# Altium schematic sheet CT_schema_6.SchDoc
size 372 x 336 mm
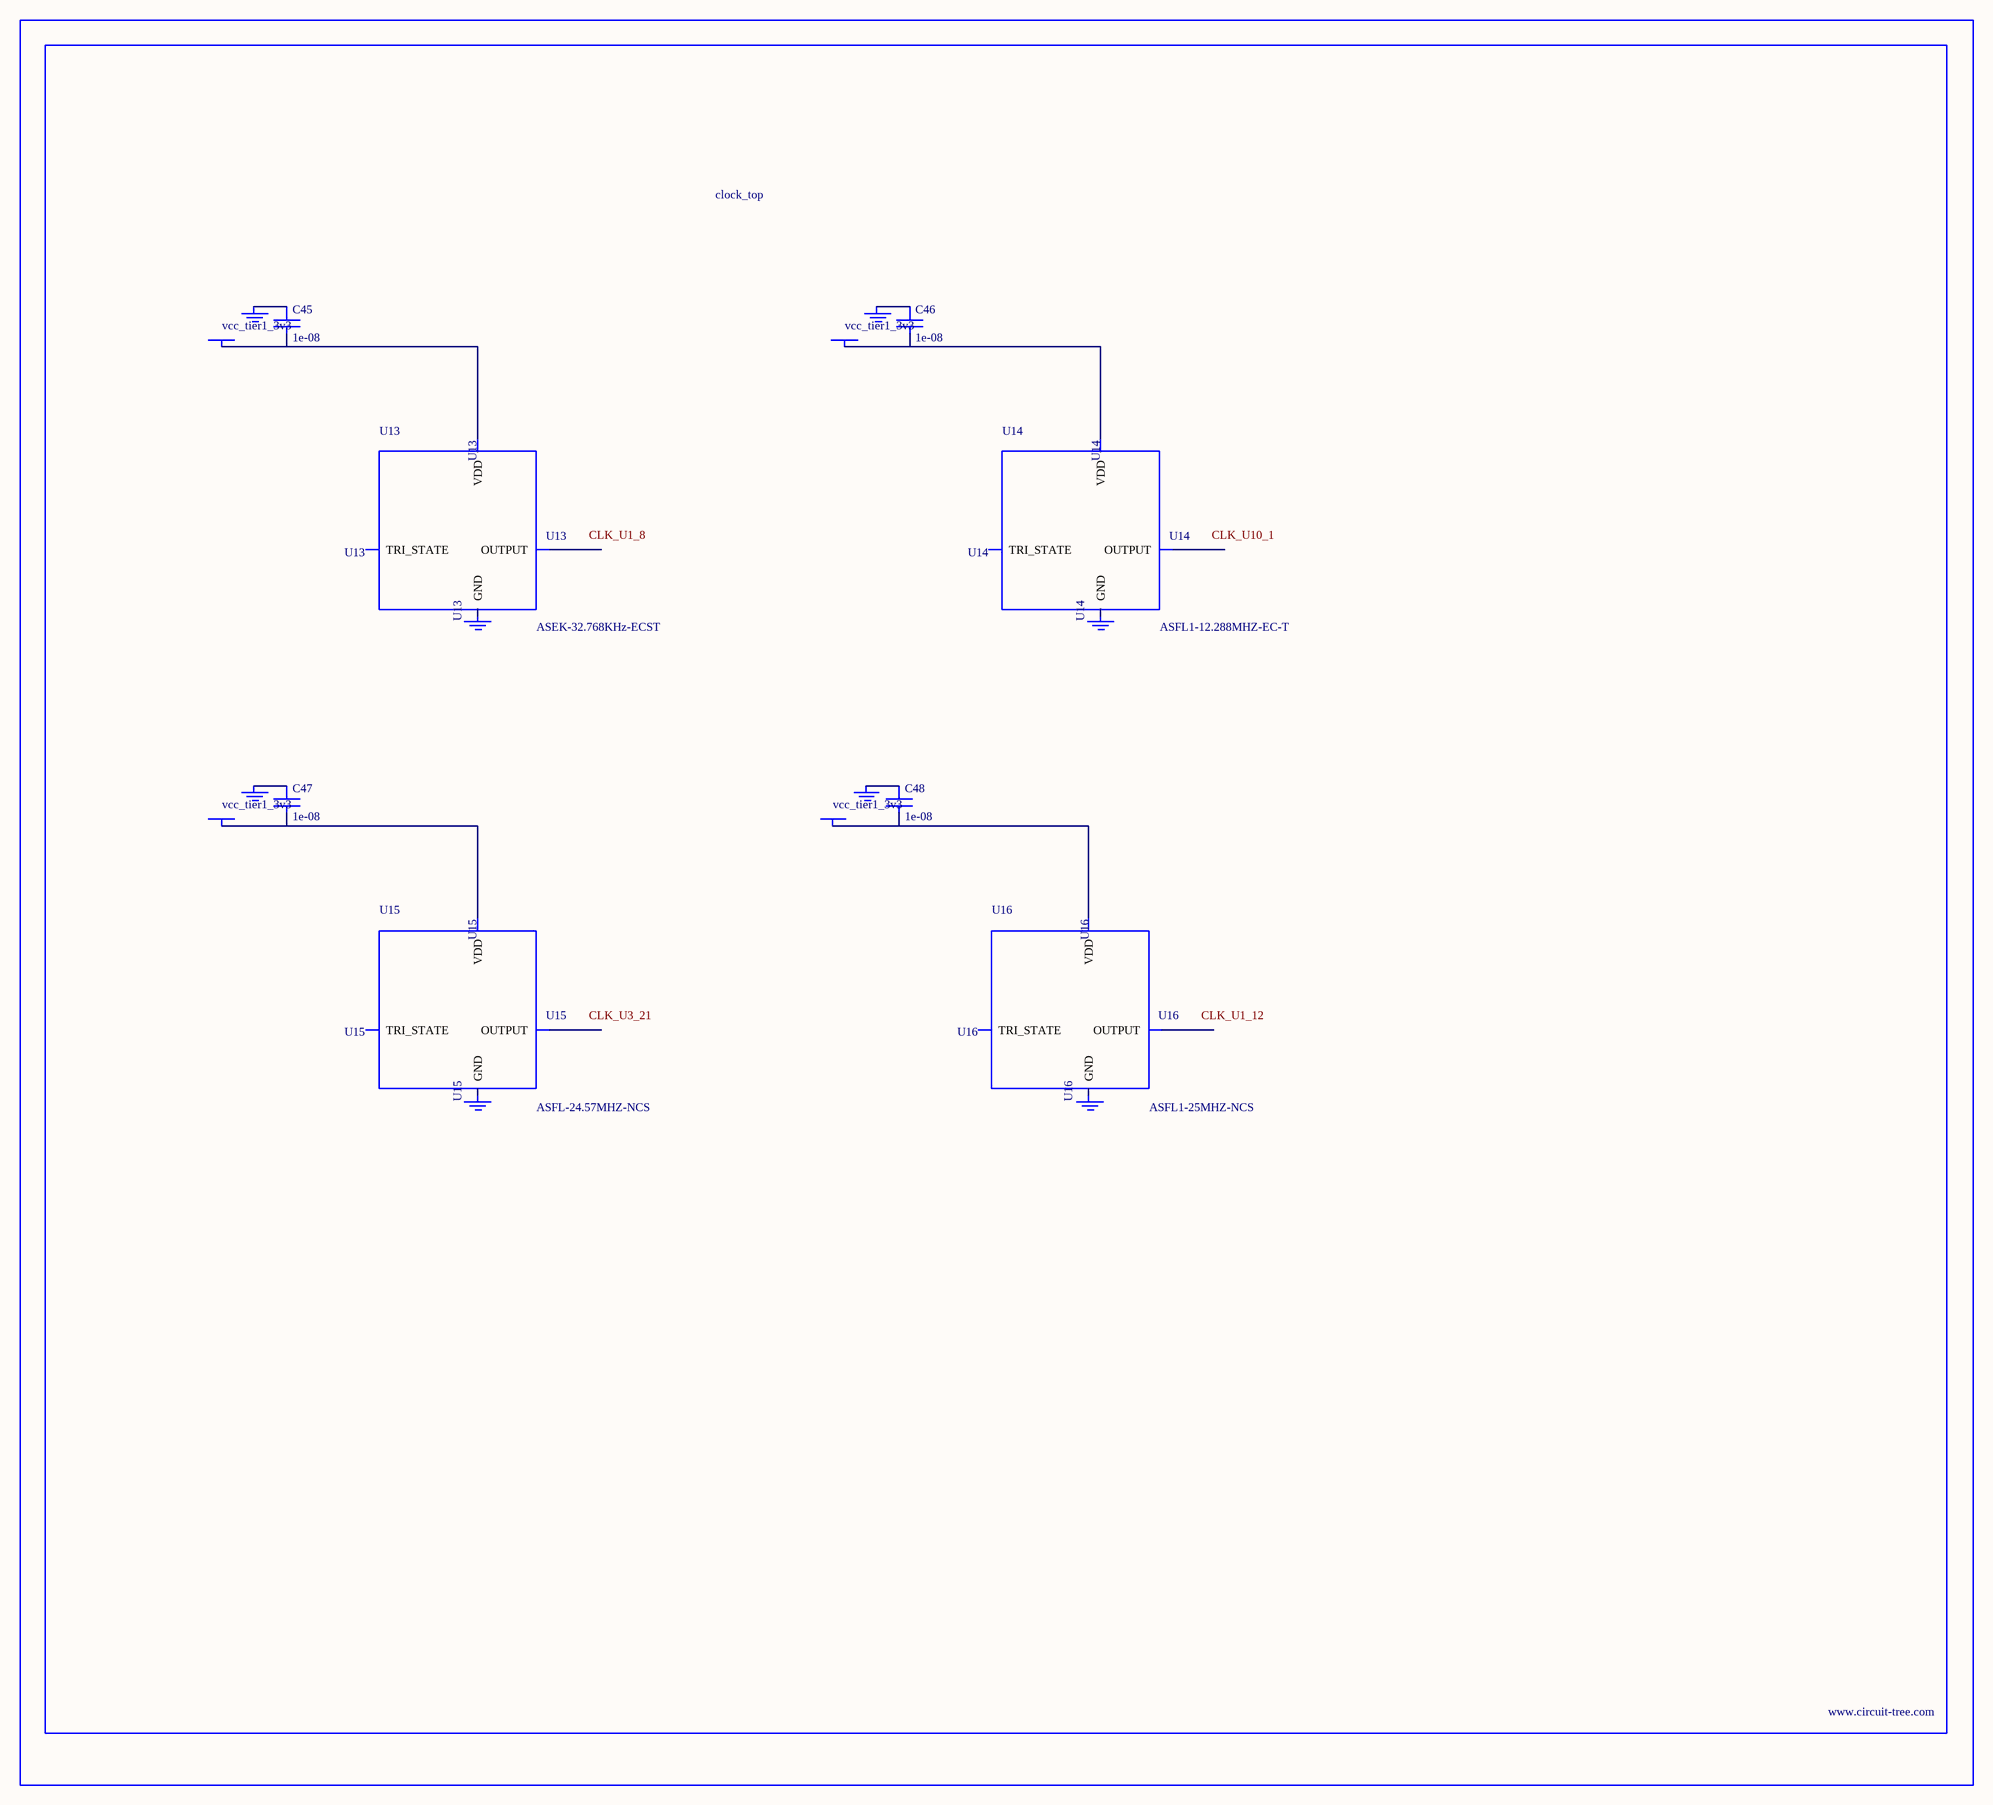
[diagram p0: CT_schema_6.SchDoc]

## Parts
BORDER5  (no value)
C45  1e-08  [C0402]
C46  1e-08  [C0402]
C47  1e-08  [C0402]
C48  1e-08  [C0402]
GND_INSTANCE_5_0  (no value)
GND_INSTANCE_5_1  (no value)
GND_INSTANCE_5_2  (no value)
GND_INSTANCE_5_3  (no value)
GND_INSTANCE_5_4  (no value)
GND_INSTANCE_5_5  (no value)
GND_INSTANCE_5_6  (no value)
GND_INSTANCE_5_7  (no value)
POWER_INSTANCE_5_0  vcc_tier1_3v3
POWER_INSTANCE_5_1  vcc_tier1_3v3
POWER_INSTANCE_5_2  vcc_tier1_3v3
POWER_INSTANCE_5_3  vcc_tier1_3v3
U13  ASEK-32.768KHz-ECST  [ASEK]
U14  ASFL1-12.288MHZ-EC-T  [ASFL1]
U15  ASFL-24.57MHZ-NCS  [ASFL1]
U16  ASFL1-25MHZ-NCS  [ASFL1]

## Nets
NetC45_1: C45.1 GND_INSTANCE_5_0.0(GND)
NetC45_2: C45.2 POWER_INSTANCE_5_0.0(PWR) U13.4(VDD)
NetC46_1: C46.1 GND_INSTANCE_5_2.0(GND)
NetC46_2: C46.2 POWER_INSTANCE_5_1.0(PWR) U14.4(VDD)
NetC47_1: C47.1 GND_INSTANCE_5_4.0(GND)
NetC47_2: C47.2 POWER_INSTANCE_5_2.0(PWR) U15.4(VDD)
NetC48_1: C48.1 GND_INSTANCE_5_6.0(GND)
NetC48_2: C48.2 POWER_INSTANCE_5_3.0(PWR) U16.4(VDD)

Not connected (* = marked no-connect by the designer): GND_INSTANCE_5_1 0(GND); GND_INSTANCE_5_3 0(GND); GND_INSTANCE_5_5 0(GND); GND_INSTANCE_5_7 0(GND); U13 1(TRI_STATE) 2(GND) 3(OUTPUT); U14 1(TRI_STATE) 2(GND) 3(OUTPUT); U15 1(TRI_STATE) 2(GND) 3(OUTPUT); U16 1(TRI_STATE) 2(GND) 3(OUTPUT)

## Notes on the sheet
- Labels drawn without touching a wire or pin: CLK_U1_8, CLK_U1_12, CLK_U3_21, CLK_U10_1

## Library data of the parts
BORDER5 = BORDER_PAGE5
C45-C48 = C0402C103K3RAC
GND_INSTANCE_5_0-GND_INSTANCE_5_7 = GND
POWER_INSTANCE_5_0-POWER_INSTANCE_5_3 = PWR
